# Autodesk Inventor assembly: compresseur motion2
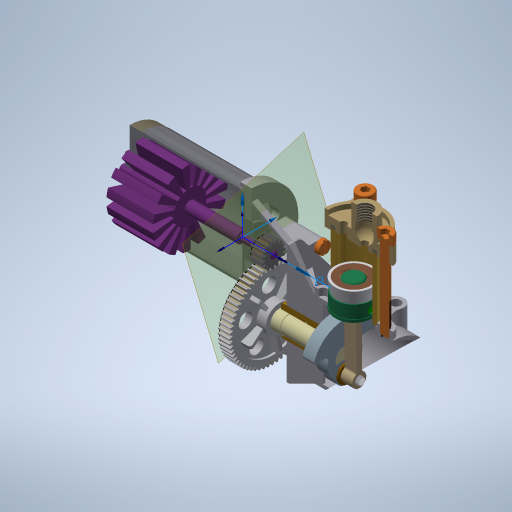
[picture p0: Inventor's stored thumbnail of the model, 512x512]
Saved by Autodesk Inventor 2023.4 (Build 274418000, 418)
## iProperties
Created: 2002-11
Part Number: compresseur motion2
Document SubType Name: Assemblage
Designer: poste-2
Control State: 0
Master: False
Checked Out: False
Shininess: 41.0
Length Units: 11269
Angle Units: 11279
Time Units: 11290
Mass Units: 11283
Length Display Precision: 3
Angle Display Precision: 2
Density: 0.0
Volumn: 0.0
Area: 0.0
PropertySet Name: Model Information
Author: poste-2
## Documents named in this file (6)
- C:\Users\bruno\Documents\1-Cours-2024-25\1-Site\Elèves\1STI2D\I2D\3.EDC-Compresseur\lib\Compresseur\Compresseur\compresseur motion.iam
- C:\Users\bruno\Documents\1-Cours-2024-25\1-Site\Elèves\1STI2D\I2D\3.EDC-Compresseur\lib\Compresseur\Compresseur\Ensemble corps.iam
- C:\Users\bruno\Documents\1-Cours-2024-25\1-Site\Elèves\1STI2D\I2D\3.EDC-Compresseur\lib\Compresseur\Compresseur\Ensemble moteur.iam
- C:\Users\bruno\Documents\1-Cours-2024-25\1-Site\Elèves\1STI2D\I2D\3.EDC-Compresseur\lib\Compresseur\Compresseur\Ensemble bielle.iam
- C:\Users\bruno\Documents\1-Cours-2024-25\1-Site\Elèves\1STI2D\I2D\3.EDC-Compresseur\lib\Compresseur\Compresseur\Ensemble piston.iam
- C:\Users\bruno\Documents\1-Cours-2024-25\1-Site\Elèves\1STI2D\I2D\3.EDC-Compresseur\lib\Compresseur\Compresseur\Ensemble manivelle.iam
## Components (5 placed, 5 different names)
1. Ensemble corps:1 [sub-assembly] — Logement:1, Plaquage:1, Plaquage:2, Plaquage:3
2. Ensemble moteur:1 [sub-assembly] — Logement:1
3. Ensemble bielle:1 [sub-assembly] — Plaquage:4, Plaquage:5, Plaquage:6
4. Ensemble piston:1 [sub-assembly] — Plaquage:1, Plaquage:5
5. Ensemble manivelle:1 [sub-assembly] — Plaquage:2, Plaquage:3, Plaquage:4, Plaquage:6
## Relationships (7: Mate 6, Insert 1)
- Logement:1 [Insert]: Ensemble corps:1 ↔ Ensemble moteur:1
- Plaquage:1 [Mate]: Ensemble corps:1 ↔ Ensemble piston:1
- Plaquage:2 [Mate]: Ensemble corps:1 ↔ Ensemble manivelle:1
- Plaquage:3 [Mate]: Ensemble corps:1 ↔ Ensemble manivelle:1
- Plaquage:4 [Mate]: Ensemble bielle:1 ↔ Ensemble manivelle:1
- Plaquage:5 [Mate]: Ensemble bielle:1 ↔ Ensemble piston:1
- Plaquage:6 [Mate]: Ensemble bielle:1 ↔ Ensemble manivelle:1
